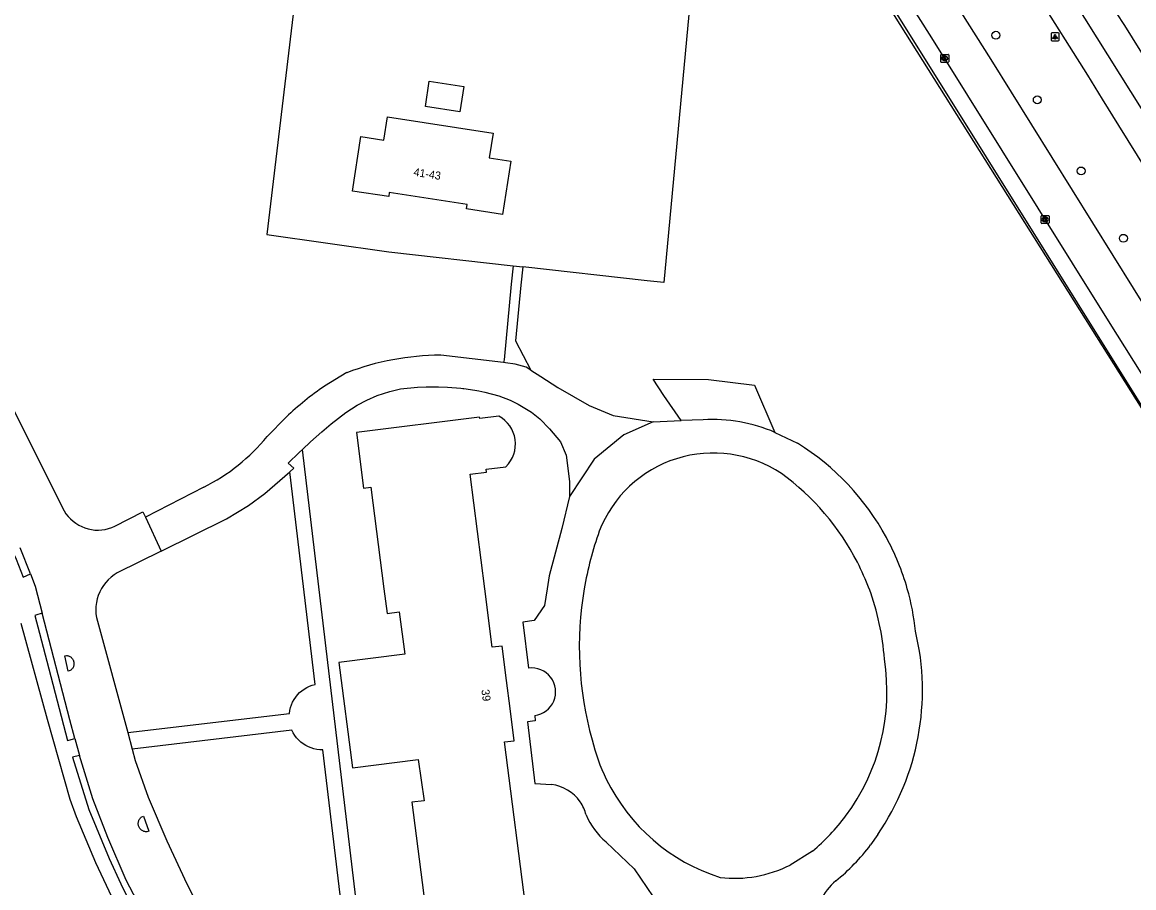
# Model space of a CAD drawing. Extents: x 158132 to 159658, y 385257 to 387209.
# Drawn here: x 159095.9 to 159234.9, y 386462.6 to 386570.8 of the extents above; entities that cross this region are included whole.
import ezdxf

# ---------------------------------------------------------------- set-up
doc = ezdxf.new("R2010")
doc.units = 0
for name, color, linetype in [('IMGEO_Boom', 7, 'Continuous'), ('IMGEO_Groenvoorziening', 7, 'Continuous'), ('IMGEO_Hek', 7, 'Continuous'), ('IMGEO_Kolk', 7, 'Continuous'), ('IMGEO_Lichtpunt', 7, 'Continuous'), ('IMGEO_Loofbos', 7, 'Continuous'), ('IMGEO_Pand', 7, 'Continuous'), ('IMGEO_Pand_nummerreeks', 7, 'Continuous'), ('IMGEO_Rijbaan_lokaal_gesloten', 7, 'Continuous'), ('IMGEO_Rijbaan_lokaal_open', 7, 'Continuous'), ('IMGEO_Rijbaan_regionaal_gesloten', 7, 'Continuous'), ('IMGEO_Voetpad_open', 7, 'Continuous')]:
    doc.layers.add(name, color=color, linetype=linetype)

msp = doc.modelspace()

# ---------------------------------------------------------------- linework, layer by layer
at = {"layer": 'IMGEO_Boom'}
for centre in [(159217.62, 386569.22), (159222.79, 386561.14), (159228.27, 386552.25), (159233.56, 386543.83)]:
    msp.add_circle(centre, 0.489, dxfattribs=at)
at = {"layer": 'IMGEO_Groenvoorziening'}
msp.add_lwpolyline([(159146.27, 386576.84), (159130.01, 386573.65), (159126.49, 386544.29), (159141.76, 386542.14), (159157.3, 386540.4)], dxfattribs=at)
at = {"layer": 'IMGEO_Hek'}
msp.add_lwpolyline([(159250.06, 386500), (159194.34, 386588.63), (159192.21, 386592.03)], dxfattribs=at)
at = {"layer": 'IMGEO_Kolk'}
for p, q in [((159210.72, 386565.9), (159210.72, 386566.76)), ((159210.79, 386566.83), (159211.65, 386566.83)), ((159211.21, 386566.61), (159211.23, 386566.61)), ((159211.72, 386566.76), (159211.72, 386565.9)), ((159211.65, 386565.83), (159210.79, 386565.83)), ((159211.23, 386566.05), (159211.2, 386566.05)), ((159223.35, 386546.68), (159224.2, 386546.68)), ((159223.27, 386545.75), (159223.27, 386546.6)), ((159224.2, 386545.68), (159223.35, 386545.68)), ((159223.76, 386546.46), (159223.78, 386546.46)), ((159223.78, 386545.9), (159223.76, 386545.9)), ((159224.27, 386546.6), (159224.27, 386545.75))]:
    msp.add_line(p, q, dxfattribs=at)
for points in [[(159210.72, 386565.9), (159210.72, 386566.76)], [(159210.79, 386566.83), (159211.65, 386566.83)], [(159211.04, 386566.53), (159211.16, 386566.53), (159211.16, 386566.38), (159211.29, 386566.53), (159211.46, 386566.53), (159211.31, 386566.38), (159211.46, 386566.13), (159211.31, 386566.13), (159211.23, 386566.29), (159211.16, 386566.23), (159211.16, 386566.13), (159211.04, 386566.13), (159211.04, 386566.53)], [(159211.72, 386566.76), (159211.72, 386565.9)], [(159211.65, 386565.83), (159210.79, 386565.83)], [(159223.35, 386546.68), (159224.2, 386546.68)], [(159223.27, 386545.75), (159223.27, 386546.6)], [(159224.2, 386545.68), (159223.35, 386545.68)], [(159223.59, 386546.38), (159223.72, 386546.38), (159223.72, 386546.23), (159223.84, 386546.38), (159224.01, 386546.38), (159223.86, 386546.23), (159224.02, 386545.98), (159223.86, 386545.98), (159223.78, 386546.14), (159223.72, 386546.07), (159223.72, 386545.98), (159223.59, 386545.98), (159223.59, 386546.38)], [(159224.27, 386546.6), (159224.27, 386545.75)]]:
    msp.add_lwpolyline(points, dxfattribs=at)
for centre, start, end in [((159210.8, 386566.75), 91.552, 178.448), ((159210.8, 386566.75), 91.552, 178.448), ((159211.64, 386566.75), 1.552, 88.448), ((159211.64, 386566.75), 1.552, 88.448), ((159210.8, 386565.91), 181.552, 268.448), ((159210.8, 386565.91), 181.552, 268.448), ((159211.64, 386565.91), 271.552, 358.448), ((159211.64, 386565.91), 271.552, 358.448), ((159223.35, 386546.6), 91.552, 178.448), ((159223.35, 386546.6), 91.552, 178.448), ((159224.2, 386546.6), 1.552, 88.448), ((159224.2, 386546.6), 1.552, 88.448), ((159223.35, 386545.75), 181.552, 268.448), ((159223.35, 386545.75), 181.552, 268.448), ((159224.2, 386545.75), 271.552, 358.448), ((159224.2, 386545.75), 271.552, 358.448)]:
    msp.add_arc(centre, 0.0765, start, end, dxfattribs=at)
for centre, major_axis, ratio, start_param, end_param in [((159211.21, 386566.33), (-0.387, 0.002), 0.722429, 4.712389, 7.853982), ((159211.23, 386566.33), (-0.39, 0.002), 0.717154, 1.570796, 4.712389), ((159223.76, 386546.18), (-0.387, 0.002), 0.722429, 4.712389, 7.853982), ((159223.78, 386546.18), (-0.39, 0.002), 0.717154, 1.570796, 4.712389)]:
    msp.add_ellipse(centre, major_axis=major_axis, ratio=ratio, start_param=start_param, end_param=end_param, dxfattribs=at)
at = {"layer": 'IMGEO_Lichtpunt'}
for p, q in [((159224.52, 386569.42), (159224.52, 386568.61)), ((159224.52, 386569.42), (159224.52, 386568.61)), ((159225.42, 386569.51), (159224.62, 386569.51)), ((159225.42, 386569.51), (159224.62, 386569.51)), ((159225.52, 386568.61), (159225.52, 386569.42)), ((159225.52, 386568.61), (159225.52, 386569.42)), ((159224.62, 386568.51), (159225.42, 386568.51)), ((159224.62, 386568.51), (159225.42, 386568.51))]:
    msp.add_line(p, q, dxfattribs=at)
for points in [[(159224.9, 386569.08), (159224.93, 386569.05), (159224.75, 386568.79), (159224.71, 386568.82), (159224.9, 386569.08)], [(159225, 386569.03), (159225.05, 386569.03), (159225.05, 386568.71), (159225, 386568.71), (159225, 386569.03)], [(159225.11, 386569.05), (159225.15, 386569.08), (159225.33, 386568.82), (159225.29, 386568.79), (159225.11, 386569.05)]]:
    msp.add_lwpolyline(points, dxfattribs=at)
msp.add_circle((159225.02, 386569.21), 0.0994, dxfattribs=at)
for centre, start, end in [((159224.62, 386569.42), 90, 180), ((159224.62, 386569.42), 90, 180), ((159225.42, 386569.42), 0, 90), ((159225.42, 386569.42), 0, 90), ((159224.62, 386568.61), 180, 270), ((159224.62, 386568.61), 180, 270), ((159225.42, 386568.61), 270, 0), ((159225.42, 386568.61), 270, 360)]:
    msp.add_arc(centre, 0.0946, start, end, dxfattribs=at)
at = {"layer": 'IMGEO_Loofbos'}
for points in [[(159168.09, 386579.39), (159179.55, 386575), (159176.11, 386538.29), (159174.04, 386538.52), (159158.49, 386540.26)], [(159178.27, 386521.04), (159176.12, 386524.17), (159174.8, 386526.21), (159181.71, 386526.16), (159187.45, 386525.47), (159190.01, 386519.54)]]:
    msp.add_lwpolyline(points, dxfattribs=at)
at = {"layer": 'IMGEO_Pand'}
for points in [[(159151.11, 386562.83), (159150.62, 386559.65), (159146.32, 386560.3), (159146.81, 386563.49), (159151.11, 386562.83)], [(159155.97, 386546.81), (159151.44, 386547.5), (159151.53, 386548.07), (159141.81, 386549.55), (159141.73, 386549.04), (159137.19, 386549.73), (159138.23, 386556.55), (159141.13, 386556.11), (159141.57, 386559), (159154.77, 386556.99), (159154.3, 386553.89), (159156.99, 386553.48), (159155.97, 386546.81)], [(159155.5, 386521.58), (159153.11, 386521.28), (159153.08, 386521.47), (159137.7, 386519.52), (159138.58, 386512.59), (159139.52, 386512.71), (159141.14, 386500), (159141.53, 386496.9), (159143.04, 386497.09), (159143.74, 386491.82), (159135.51, 386490.77), (159137.19, 386477.61), (159145.42, 386478.66), (159146.15, 386473.48), (159144.64, 386473.29), (159146.66, 386457.42), (159145.54, 386457.28), (159146.41, 386450.43)], [(159163.46, 386459.26), (159161.1, 386458.96), (159161.05, 386459.36), (159158.99, 386459.1), (159156.22, 386480.84), (159157.42, 386480.99), (159156.91, 386485.02), (159156.46, 386488.53), (159155.92, 386492.83), (159154.68, 386492.67), (159153.74, 386500), (159151.92, 386514.32), (159153.96, 386514.58), (159153.92, 386514.96), (159156.38, 386515.26)]]:
    msp.add_lwpolyline(points, dxfattribs=at)
msp.add_arc((159153.59, 386518.09), 3.98, 314.6535, 61.2893, dxfattribs=at)
at = {"layer": 'IMGEO_Rijbaan_lokaal_gesloten'}
for points in [[(159156.1, 386528.28), (159148.23, 386529.21)], [(159159.49, 386527.35), (159158.92, 386527.72), (159157.52, 386528.08), (159156.35, 386528.25), (159156.1, 386528.28)], [(159159.49, 386527.35), (159160.75, 386526.52), (159162.89, 386525.18), (159166.8, 386522.9), (159169.77, 386521.66), (159174.79, 386520.88)], [(159136.49, 386527.02), (159133.72, 386525.35)], [(159130.94, 386517.43), (159131.94, 386518.36), (159133.37, 386519.64), (159134.55, 386520.62), (159136.37, 386522.02), (159137.8, 386522.96), (159138.99, 386523.6), (159140.28, 386524.15), (159141.86, 386524.68), (159143.22, 386524.99), (159145.33, 386525.22), (159146.4, 386525.26), (159147.94, 386525.25), (159149.07, 386525.21), (159150.75, 386525.07), (159151, 386525.05), (159151.12, 386525.03), (159152.51, 386524.84), (159153.01, 386524.74), (159153.37, 386524.67), (159153.76, 386524.6), (159155.49, 386524.12), (159156.93, 386523.57), (159157.93, 386523.09), (159159.6, 386522.06), (159160.62, 386521.24), (159161.85, 386520), (159163.2, 386518.37), (159163.9, 386516.72), (159164.33, 386513.4), (159164.32, 386511.52)], [(159128.92, 386521.47), (159126.55, 386519.04)], [(159174.79, 386520.88), (159171.12, 386519.25), (159167.43, 386516.2), (159164.32, 386511.52)], [(159174.79, 386520.88), (159178.27, 386521.04)], [(159181.05, 386521.12), (159178.27, 386521.04)], [(159190.01, 386519.54), (159192.83, 386518.2)], [(159129.36, 386514.61), (159129.89, 386515.08), (159129.16, 386515.72), (159130.54, 386517.05), (159130.94, 386517.43)], [(159113.31, 386504.7), (159121.48, 386508.75), (159124.21, 386510.4), (159126.27, 386511.9), (159129.36, 386514.61)], [(159118.62, 386512.71), (159111.35, 386508.93)], [(159164.32, 386511.52), (159163.38, 386507.51), (159161.8, 386501.6), (159161.54, 386500), (159161.2, 386497.88), (159159.92, 386496.01), (159158.48, 386495.81), (159159.22, 386490.06)], [(159111.35, 386508.93), (159113.31, 386504.7)], [(159159.98, 386484.13), (159160.04, 386483.48), (159159.1, 386483.35), (159160.01, 386475.65), (159162.07, 386475.51)], [(159202.88, 386469.27), (159201.96, 386467.95)], [(159168.9, 386468.32), (159172.42, 386464.95), (159174.8, 386461.48)], [(159194.7, 386467.19), (159191.92, 386465.44)]]:
    msp.add_lwpolyline(points, dxfattribs=at)
for centre, radius, start, end in [((159148.48, 386495.28), 33.93, 90.4295, 110.7037), ((159156.85, 386491.81), 40.74, 124.5982, 133.2841), ((159182.13, 386501.04), 20.12, 66.9352, 93.0802), ((159107.96, 386534.19), 23.98, 296.3821, 320.8034), ((159176.12, 386491.33), 31.64, 28.4871, 58.1064), ((159182.32, 386501.67), 15.3, 56.3026, 158.8201), ((159172.41, 386489.02), 31.35, 27.1055, 54.0571), ((159208.43, 386492.79), 42.87, 160.3649, 170.3228), ((159176.14, 386491.34), 31.62, 15.8888, 28.4926), ((159172.57, 386489.09), 31.17, 20.476, 27.1205), ((159208.55, 386492.76), 43, 170.3033, 195.7156), ((159172.41, 386489.03), 31.35, 3.9543, 20.4927), ((159175.99, 386491.32), 31.77, 6.0783, 15.8613), ((159176.49, 386487.29), 31.95, 325.6699, 13.3646), ((159178.07, 386487.1), 25.94, 323.2063, 9.0718), ((159159.61, 386487.1), 2.99, 277.0744, 97.4962), ((159190.45, 386486.69), 23.95, 193.4594, 206.0015), ((159190.44, 386486.69), 23.94, 206.0142, 252.3223), ((159161.49, 386470.47), 5.07, 34.772, 83.437), ((159161.51, 386470.48), 5.05, 13.9839, 34.7896), ((159174.68, 386475.21), 8.99, 202.9473, 229.974), ((159178.07, 386487.09), 25.93, 309.8934, 323.2182), ((159180.84, 386484.02), 26.54, 309.2185, 322.7284), ((159184.96, 386479.18), 15.4, 263.3265, 296.8575), ((159202.49, 386457.69), 7.56, 130.1649, 154.13)]:
    msp.add_arc(centre, radius, start, end, dxfattribs=at)
at = {"layer": 'IMGEO_Rijbaan_lokaal_open'}
for points in [[(159255, 386496.36), (159253.77, 386498.34), (159252.73, 386500), (159231.68, 386533.49), (159209.62, 386568.89), (159197.67, 386587.77), (159196.24, 386590.04), (159191.93, 386597.03), (159189.83, 386600.39), (159188.27, 386602.91)], [(159237.38, 386533.49), (159217.04, 386566.17), (159211.42, 386575.11)], [(159086.18, 386539.58), (159101.17, 386509.73), (159101.4, 386509.38), (159101.67, 386509.04), (159101.96, 386508.73), (159102.28, 386508.44), (159102.62, 386508.18), (159102.99, 386507.96), (159103.37, 386507.76), (159103.77, 386507.6), (159104.18, 386507.48), (159104.6, 386507.39), (159105.02, 386507.34), (159105.45, 386507.33), (159105.88, 386507.36), (159106.3, 386507.42), (159106.72, 386507.52), (159107.12, 386507.66), (159107.52, 386507.83), (159110.99, 386509.61), (159111.35, 386508.93)], [(159096.98, 386501.85), (159095.67, 386505.1)], [(159113.31, 386504.7), (159107.81, 386501.98), (159107.41, 386501.73), (159107.04, 386501.44), (159106.69, 386501.13), (159106.37, 386500.78), (159106.08, 386500.41), (159105.83, 386500.02), (159105.61, 386499.6), (159105.44, 386499.16), (159105.3, 386498.72), (159105.2, 386498.26), (159105.14, 386497.79), (159105.12, 386497.32), (159105.15, 386496.85), (159105.22, 386496.39), (159109.11, 386482.01)], [(159096.98, 386501.85), (159097.53, 386500.31), (159098.43, 386496.92)], [(159102.52, 386481.25), (159101.87, 386483.6), (159098.43, 386496.92)], [(159102.06, 386489.87), (159101.99, 386489.81), (159101.92, 386489.76), (159101.67, 386489.7), (159101.24, 386491.59), (159101.46, 386491.66), (159101.55, 386491.64), (159101.64, 386491.62), (159101.72, 386491.6), (159101.8, 386491.57), (159101.88, 386491.53), (159101.96, 386491.48), (159102.03, 386491.43), (159102.1, 386491.37), (159102.15, 386491.3), (159102.21, 386491.23), (159102.26, 386491.16), (159102.3, 386491.08), (159102.34, 386491), (159102.36, 386490.92), (159102.39, 386490.83), (159102.4, 386490.74), (159102.4, 386490.66), (159102.4, 386490.57), (159102.39, 386490.48), (159102.38, 386490.39), (159102.35, 386490.31), (159102.32, 386490.23), (159102.28, 386490.15), (159102.24, 386490.07), (159102.18, 386490), (159102.13, 386489.93), (159102.06, 386489.87)], [(159109.11, 386482.01), (159109.67, 386479.93)], [(159102.52, 386481.25), (159103.08, 386479.14)], [(159109.67, 386479.93), (159110.05, 386478.53), (159111.67, 386473.93), (159114, 386468.46), (159116.52, 386463.07), (159119.22, 386457.77), (159121.92, 386453.72), (159124.19, 386450.76), (159126.43, 386448.09)], [(159113.14, 386455.52), (159108.94, 386463.56), (159106.64, 386468.87), (159104.74, 386473.72), (159103.08, 386479.14)], [(159110.91, 386469.76), (159110.83, 386469.82), (159110.76, 386469.87), (159110.7, 386469.94), (159110.64, 386470.01), (159110.59, 386470.09), (159110.55, 386470.16), (159110.51, 386470.25), (159110.48, 386470.33), (159110.46, 386470.42), (159110.44, 386470.51), (159110.44, 386470.6), (159110.44, 386470.7), (159110.45, 386470.79), (159110.46, 386470.88), (159110.49, 386470.96), (159110.52, 386471.05), (159110.56, 386471.13), (159110.61, 386471.21), (159110.67, 386471.28), (159110.73, 386471.35), (159110.79, 386471.41), (159110.86, 386471.47), (159111.08, 386471.56), (159111.74, 386469.67), (159111.51, 386469.6), (159111.42, 386469.6), (159111.33, 386469.6), (159111.24, 386469.62), (159111.15, 386469.65), (159111.07, 386469.68), (159110.99, 386469.72), (159110.91, 386469.76)]]:
    msp.add_lwpolyline(points, dxfattribs=at)
at = {"layer": 'IMGEO_Rijbaan_regionaal_gesloten'}
for points in [[(159337.59, 386396.88), (159259.04, 386523.03), (159222.99, 386580.57)], [(159334.62, 386395.01), (159326.35, 386408.09), (159320.18, 386417.89), (159312.88, 386429.61), (159302.23, 386446.71), (159294.43, 386459.19), (159268.99, 386500), (159264.8, 386506.73), (159232.99, 386557.93), (159230.94, 386561.23), (159229.11, 386564.24), (159222.73, 386574.37), (159219.83, 386578.66)], [(159232.64, 386572.02), (159233.68, 386570.42), (159242.94, 386555.56), (159253.77, 386538.11), (159277.62, 386500), (159288.12, 386483.23), (159318.51, 386434.33), (159340.68, 386398.8)]]:
    msp.add_lwpolyline(points, dxfattribs=at)
at = {"layer": 'IMGEO_Voetpad_open'}
for points in [[(159253.15, 386495.23), (159250.17, 386500), (159194.12, 386589.79), (159192.73, 386592.19)], [(159157.3, 386540.4), (159157.04, 386538.09), (159156.17, 386528.64), (159156.1, 386528.28)], [(159157.3, 386540.4), (159158.49, 386540.26)], [(159158.49, 386540.26), (159158.23, 386537.96), (159157.57, 386530.99), (159159.49, 386527.35)], [(159139.8, 386443.12), (159130.94, 386517.43)], [(159109.11, 386482.01), (159129.32, 386484.41), (159129.37, 386484.78), (159129.46, 386485.14), (159129.58, 386485.48), (159129.73, 386485.82), (159129.91, 386486.14), (159130.11, 386486.45), (159130.35, 386486.73), (159130.6, 386487), (159130.88, 386487.23), (159131.18, 386487.45), (159131.5, 386487.64), (159131.83, 386487.79), (159132.18, 386487.92), (159132.53, 386488.02), (159129.36, 386514.61)], [(159094.3, 386505.54), (159095.16, 386503.71), (159096.05, 386501.45), (159096.98, 386501.85)], [(159098.43, 386496.92), (159097.63, 386496.69), (159097.51, 386496.66), (159098.09, 386494.42), (159099.25, 386489.99), (159101.6, 386481.01), (159101.74, 386481.06), (159102.52, 386481.25)], [(159112.67, 386450.53), (159110.57, 386454.48), (159107.78, 386460.06), (159105.15, 386465.72), (159102.7, 386471.45), (159101.94, 386473.64), (159099.08, 386483.66), (159095.79, 386495.63)], [(159137.91, 386442.87), (159133.51, 386479.83), (159133.13, 386479.84), (159132.76, 386479.89), (159132.39, 386479.96), (159132.04, 386480.08), (159131.69, 386480.22), (159131.36, 386480.39), (159131.05, 386480.59), (159130.75, 386480.82), (159130.48, 386481.08), (159130.23, 386481.35), (159130.01, 386481.66), (159129.81, 386481.98), (159129.64, 386482.31), (159109.67, 386479.93)], [(159103.08, 386479.14), (159102.22, 386478.95), (159104.26, 386472.38), (159106.78, 386466.27), (159108.25, 386463.08), (159110.04, 386459.45), (159113.61, 386452.78)]]:
    msp.add_lwpolyline(points, dxfattribs=at)

# ---------------------------------------------------------------- texts
at = {"layer": 'IMGEO_Pand_nummerreeks'}
for s, rotation, p in [('41-43', 351.1791, (159144.79, 386551.65)), ('39', 277.6201, (159153.31, 386487.34))]:
    msp.add_text(s, height=1, rotation=rotation, dxfattribs=at).set_placement(p)

doc.saveas('drawing.dxf')
